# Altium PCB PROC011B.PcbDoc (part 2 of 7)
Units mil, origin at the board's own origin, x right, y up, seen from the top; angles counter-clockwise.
Board outline 3304 x 2569 mil, 6 copper layers (TOP, L2-GND1, L3-GND/SIG, L4-GND/SIG, L5-GND2, BOTTOM), stack 55.77 mil thick; 376 components, 289 nets, 1284 pads, 1755 vias.
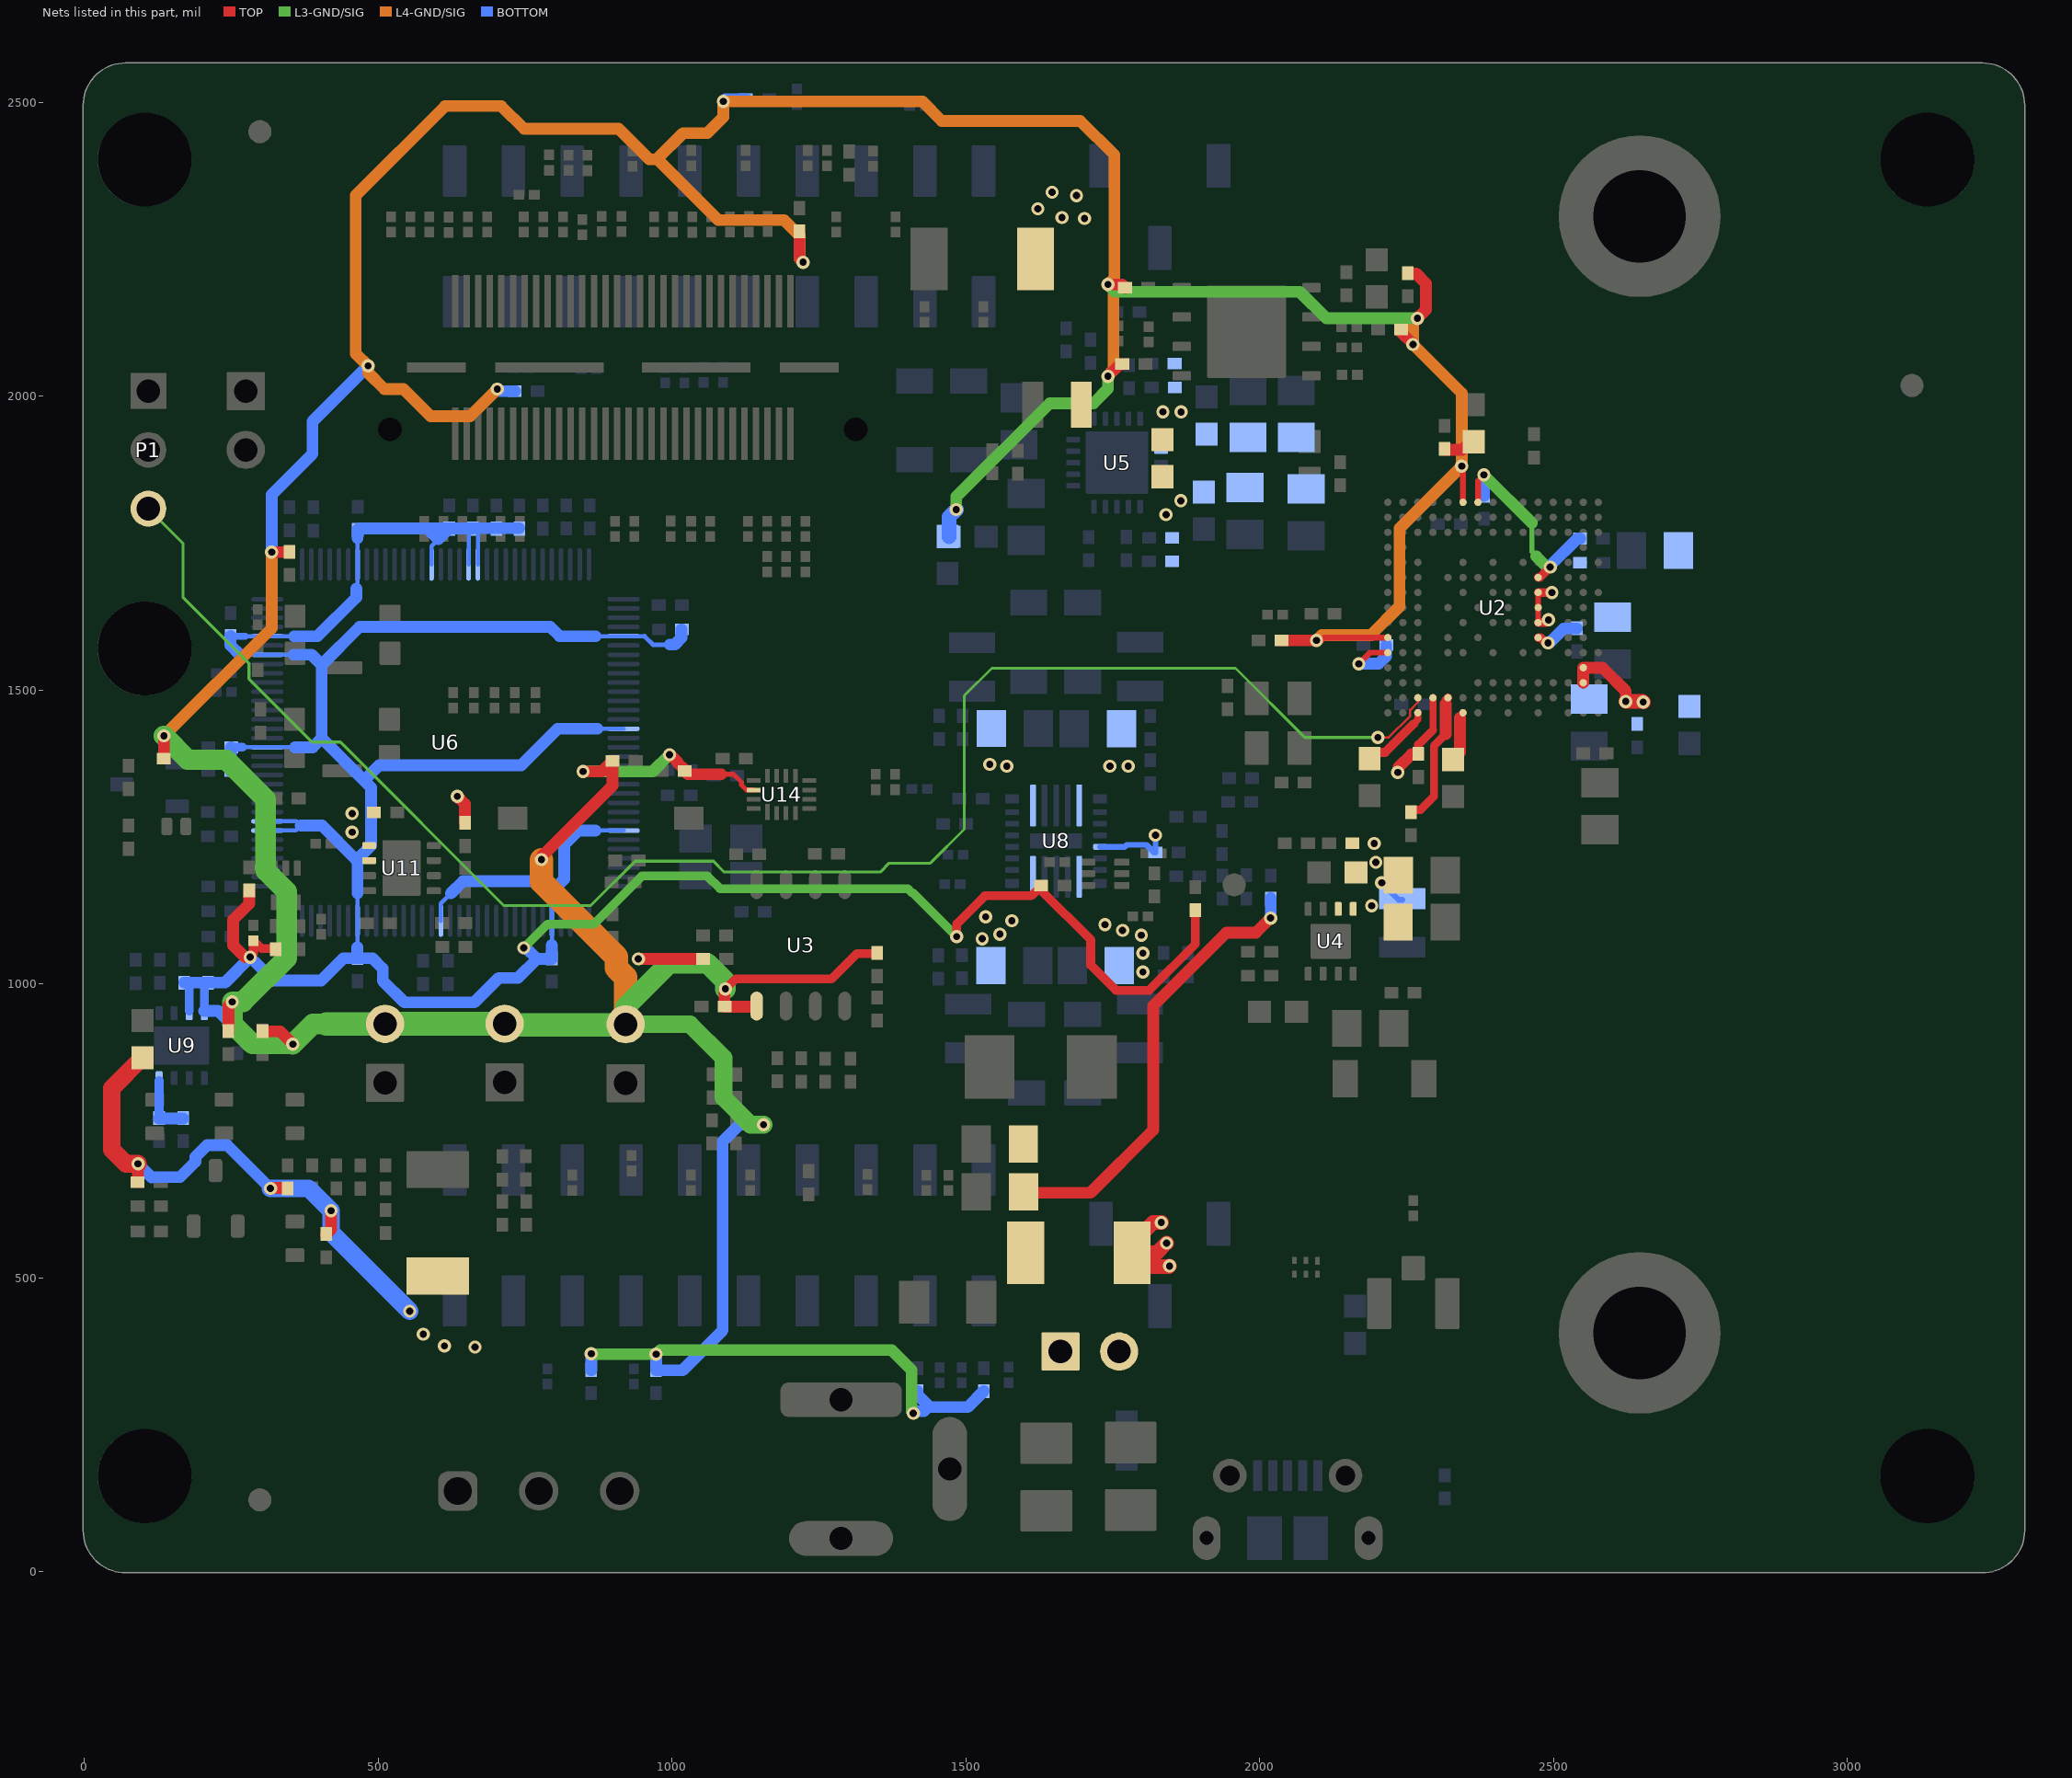
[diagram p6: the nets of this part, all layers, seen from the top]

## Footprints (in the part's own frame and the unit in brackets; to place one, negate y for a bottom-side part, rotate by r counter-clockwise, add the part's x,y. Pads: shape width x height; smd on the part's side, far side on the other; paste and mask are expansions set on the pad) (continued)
PDT0128A [mm] "Thin QFP, 128-Leads, Body 14x14mm, Pitch 0.4mm"
  oval 1.4x0.2 smd: 1(-7.7,6.2) 2(-7.7,5.8) 3(-7.7,5.4) 4(-7.7,5) 5(-7.7,4.6) 6(-7.7,4.2) 7(-7.7,3.8) 8(-7.7,3.4) 9(-7.7,3) 10(-7.7,2.6) 11(-7.7,2.2) 12(-7.7,1.8) 13(-7.7,1.4) 14(-7.7,1) 15(-7.7,0.6) 16(-7.7,0.2) 17(-7.7,-0.2) 18(-7.7,-0.6) 19(-7.7,-1) 20(-7.7,-1.4) 21(-7.7,-1.8) 22(-7.7,-2.2) 23(-7.7,-2.6) 24(-7.7,-3) 25(-7.7,-3.4) 26(-7.7,-3.8) 27(-7.7,-4.2) 28(-7.7,-4.6) 29(-7.7,-5) 30(-7.7,-5.4) 31(-7.7,-5.8) 32(-7.7,-6.2) 65(7.7,-6.2) 66(7.7,-5.8) 67(7.7,-5.4) 68(7.7,-5) 69(7.7,-4.6) 70(7.7,-4.2) 71(7.7,-3.8) 72(7.7,-3.4) 73(7.7,-3) 74(7.7,-2.6) 75(7.7,-2.2) 76(7.7,-1.8) 77(7.7,-1.4) 78(7.7,-1) 79(7.7,-0.6) 80(7.7,-0.2) 81(7.7,0.2) 82(7.7,0.6) 83(7.7,1) 84(7.7,1.4) 85(7.7,1.8) 86(7.7,2.2) 87(7.7,2.6) 88(7.7,3) 89(7.7,3.4) 90(7.7,3.8) 91(7.7,4.2) 92(7.7,4.6) 93(7.7,5) 94(7.7,5.4) 95(7.7,5.8) 96(7.7,6.2)
  oval 0.2x1.4 smd: 33(-6.2,-7.7) 34(-5.8,-7.7) 35(-5.4,-7.7) 36(-5,-7.7) 37(-4.6,-7.7) 38(-4.2,-7.7) 39(-3.8,-7.7) 40(-3.4,-7.7) 41(-3,-7.7) 42(-2.6,-7.7) 43(-2.2,-7.7) 44(-1.8,-7.7) 45(-1.4,-7.7) 46(-1,-7.7) 47(-0.6,-7.7) 48(-0.2,-7.7) 49(0.2,-7.7) 50(0.6,-7.7) 51(1,-7.7) 52(1.4,-7.7) 53(1.8,-7.7) 54(2.2,-7.7) 55(2.6,-7.7) 56(3,-7.7) 57(3.4,-7.7) 58(3.8,-7.7) 59(4.2,-7.7) 60(4.6,-7.7) 61(5,-7.7) 62(5.4,-7.7) 63(5.8,-7.7) 64(6.2,-7.7) 97(6.2,7.7) 98(5.8,7.7) 99(5.4,7.7) 100(5,7.7) 101(4.6,7.7) 102(4.2,7.7) 103(3.8,7.7) 104(3.4,7.7) 105(3,7.7) 106(2.6,7.7) 107(2.2,7.7) 108(1.8,7.7) 109(1.4,7.7) 110(1,7.7) 111(0.6,7.7) 112(0.2,7.7) 113(-0.2,7.7) 114(-0.6,7.7) 115(-1,7.7) 116(-1.4,7.7) 117(-1.8,7.7) 118(-2.2,7.7) 119(-2.6,7.7) 120(-3,7.7) 121(-3.4,7.7) 122(-3.8,7.7) 123(-4.2,7.7) 124(-4.6,7.7) 125(-5,7.7) 126(-5.4,7.7) 127(-5.8,7.7) 128(-6.2,7.7)
  silkscreen extent -7.7,-6.3 6.3,6.99, body extent -8,-8 8,8, height 1.07
RNF0026C [mm] "QFN, 26-Leads, Body 4x4.5mm, Pitch 0.5mm"
  rrect25% 0.6x0.4 smd paste-0.3: 1(-1.9,1.825) 8(-1.9,-1.825) 14(1.9,-1.825) 21(1.9,1.825)
  rrect40% 0.6x0.25 smd paste+0: 2(-1.9,1.25) 3(-1.9,0.75) 4(-1.9,0.25) 5(-1.9,-0.25) 6(-1.9,-0.75) 7(-1.9,-1.25) 15(1.9,-1.25) 16(1.9,-0.75) 17(1.9,-0.25) 18(1.9,0.25) 19(1.9,0.75) 20(1.9,1.25)
  rrect40% 0.25x1.82 smd paste-1: 9(-1,-1.54) 10(-0.5,-1.54) 11(0,-1.54) 12(0.5,-1.54) 13(1,-1.54) 22(1,1.54) 23(0.5,1.54) 24(0,1.54) 25(-0.5,1.54) 26(-1,1.54)
  rrect15% 2.24x0.66 smd paste-1: 27(0,0)
  rrect50% 0.6x0.3 on Bottom Paste: ""(-1.9,-1.775) ""(-1.9,1.775) ""(1.9,-1.775) ""(1.9,1.775)
  rrect50% 0.3x0.825 on Bottom Paste: ""(-1.575,-2.037) ""(-1.575,2.037) ""(1.575,-2.037) ""(1.575,2.037)
  rrect50% 0.25x0.81 on Bottom Paste: ""(-1,-2.045) ""(-1,-1.035) ""(-1,1.035) ""(-1,2.045) ""(-0.5,-2.045) ""(-0.5,-1.035) ""(-0.5,1.035) ""(-0.5,2.045) ""(0,-2.045) ""(0,-1.035) ""(0,1.035) ""(0,2.045) ""(0.5,-2.045) ""(0.5,-1.035) ""(0.5,1.035) ""(0.5,2.045) ""(1,-2.045) ""(1,-1.035) ""(1,1.035) ""(1,2.045)
  rrect50% 0.98x0.66 on Bottom Paste: ""(-0.59,0) ""(0.59,0)
  TOP region: -1.775,-2.4 -1.775,-1.675 -1.775,-1.665 -1.767,-1.647 -1.753,-1.633 -1.735,-1.625 -1.725,-1.625 -1.725,-1.625 -1.475,-1.625 -1.465,-1.625 -1.447,-1.633 -1.433,-1.647 -1.425,-1.665 -1.425,-1.675 -1.425,-1.675 -1.425,-2.4 -1.425,-2.41 -1.433,-2.428 -1.447,-2.442 -1.465,-2.45 -1.475,-2.45 -1.475,-2.45 -1.725,-2.45 -1.735,-2.45 -1.753,-2.442 -1.767,-2.428 -1.775,-2.41 -1.775,-2.4
  TOP region: 1.425,-2.4 1.425,-1.675 1.425,-1.665 1.433,-1.647 1.447,-1.633 1.465,-1.625 1.475,-1.625 1.475,-1.625 1.725,-1.625 1.735,-1.625 1.753,-1.633 1.767,-1.647 1.775,-1.665 1.775,-1.675 1.775,-1.675 1.775,-2.4 1.775,-2.41 1.767,-2.428 1.753,-2.442 1.735,-2.45 1.725,-2.45 1.725,-2.45 1.475,-2.45 1.465,-2.45 1.447,-2.442 1.433,-2.428 1.425,-2.41 1.425,-2.4
  TOP region: 1.425,1.675 1.425,2.4 1.425,2.41 1.433,2.428 1.447,2.442 1.465,2.45 1.475,2.45 1.475,2.45 1.725,2.45 1.735,2.45 1.753,2.442 1.767,2.428 1.775,2.41 1.775,2.4 1.775,2.4 1.775,1.675 1.775,1.665 1.767,1.647 1.753,1.633 1.735,1.625 1.725,1.625 1.725,1.625 1.475,1.625 1.465,1.625 1.447,1.633 1.433,1.647 1.425,1.665 1.425,1.675
  TOP region: -1.775,1.675 -1.775,2.4 -1.775,2.41 -1.767,2.428 -1.753,2.442 -1.735,2.45 -1.725,2.45 -1.725,2.45 -1.475,2.45 -1.465,2.45 -1.447,2.442 -1.433,2.428 -1.425,2.41 -1.425,2.4 -1.425,2.4 -1.425,1.675 -1.425,1.665 -1.433,1.647 -1.447,1.633 -1.465,1.625 -1.475,1.625 -1.475,1.625 -1.725,1.625 -1.735,1.625 -1.753,1.633 -1.767,1.647 -1.775,1.665 -1.775,1.675
  silkscreen extent -2.45,-2.7 2.45,2.7, body extent -2,-2.25 2,2.25, height 0.9
RSV0016A [mm] "QFN, 16-Leads, Body 1.8x2.6mm, Pitch 0.4mm, TI Recommended"
  rect 0.7x0.2 smd: 1(-0.75,0.6)
  rect 0.6x0.2 smd: 2(-0.8,0.2) 3(-0.8,-0.2) 4(-0.8,-0.6) 9(0.8,-0.6) 10(0.8,-0.2) 11(0.8,0.2) 12(0.8,0.6)
  rect 0.2x0.6 smd: 5(-0.6,-1.2) 6(-0.2,-1.2) 7(0.2,-1.2) 8(0.6,-1.2) 13(0.6,1.2) 14(0.2,1.2) 15(-0.2,1.2) 16(-0.6,1.2)
  silkscreen extent -1.08,-1.33 1.08,1.45, body extent -0.92,-1.32 0.92,1.33, height 0.56
RTJ0020D [mm] "QFN, 20-Leads, Body 4x4mm, Pitch 0.5mm, Thermal Pad 2.7x2.7mm, TI Recommended"
  rrect42% 0.6x0.24 smd: 1(-1.9,1) 2(-1.9,0.5) 3(-1.9,0) 4(-1.9,-0.5) 5(-1.9,-1) 11(1.9,-1) 12(1.9,-0.5) 13(1.9,0) 14(1.9,0.5) 15(1.9,1)
  rrect42% 0.24x0.6 smd: 6(-1,-1.9) 7(-0.5,-1.9) 8(0,-1.9) 9(0.5,-1.9) 10(1,-1.9) 16(1,1.9) 17(0.5,1.9) 18(0,1.9) 19(-0.5,1.9) 20(-1,1.9)
  rrect50% 1.19x1.19 on Bottom Paste: 21(-0.695,-0.695) 21(-0.695,0.695) 21(0.695,-0.695) 21(0.695,0.695)
  rrect4% 2.7x2.7 smd paste-1.4: 21(0,0)
  silkscreen extent -2.22,-2.22 2.23,2.22, body extent -2.07,-2.07 2.08,2.08, height 0.8
SAMTEC_QSH-030-01-X-D-A [mm] "Receptacle, 0.5 mm, 30x2, TH"
  rect 2.27x0.279 smd: 1(-2.865,7.25) 2(2.865,7.25) 3(-2.865,6.75) 4(2.865,6.75) 5(-2.865,6.25) 6(2.865,6.25) 7(-2.865,5.75) 8(2.865,5.75) 9(-2.865,5.25) 10(2.865,5.25) 11(-2.865,4.75) 12(2.865,4.75) 13(-2.865,4.25) 14(2.865,4.25) 15(-2.865,3.75) 16(2.865,3.75) 17(-2.865,3.25) 18(2.865,3.25) 19(-2.865,2.75) 20(2.865,2.75) 21(-2.865,2.25) 22(2.865,2.25) 23(-2.865,1.75) 24(2.865,1.75) 25(-2.865,1.25) 26(2.865,1.25) 27(-2.865,0.75) 28(2.865,0.75) 29(-2.865,0.25) 30(2.865,0.25) 31(-2.865,-0.25) 32(2.865,-0.25) 33(-2.865,-0.75) 34(2.865,-0.75) 35(-2.865,-1.25) 36(2.865,-1.25) 37(-2.865,-1.75) 38(2.865,-1.75) 39(-2.865,-2.25) 40(2.865,-2.25) 41(-2.865,-2.75) 42(2.865,-2.75) 43(-2.865,-3.25) 44(2.865,-3.25) 45(-2.865,-3.75) 46(2.865,-3.75) 47(-2.865,-4.25) 48(2.865,-4.25) 49(-2.865,-4.75) 50(2.865,-4.75) 51(-2.865,-5.25) 52(2.865,-5.25) 53(-2.865,-5.75) 54(2.865,-5.75) 55(-2.865,-6.25) 56(2.865,-6.25) 57(-2.865,-6.75) 58(2.865,-6.75) 59(-2.865,-7.25) 60(2.865,-7.25)
  round 0 hole 1.02 unplated mask+0.127: MH1(2.67,10.065) MH2(2.67,-10.065)
  rect 0.43x2.54 smd: MP1(0,8.065) MP4(0,-8.065)
  rect 0.43x4.7 smd: MP2(0,3.175) MP3(0,-3.175)
  silkscreen extent -3.9,-10.66 3.62,10.66, body extent -3.75,-10.64 3.75,10.67, height 3.25
SAMTEC_SSM-103-X-SV [mm] "Receptacle, 2.54mm, 3x1, SMT"
  rrect10% 1.02x1.905 smd: 1(-2.54,-1.777) 2(0,1.777) 3(2.54,-1.777)
  silkscreen extent -3.81,-2.27 3.81,1.28, body extent -3.81,-2.29 3.81,2.29, height 7.51
SAMTEC_SSM-110-X-DV [mm] "Receptacle, 2.54mm, 10x2, SMT"
  rrect10% 1.02x2.22 smd: 1(-11.43,2.825) 2(-11.43,-2.825) 3(-8.89,2.825) 4(-8.89,-2.825) 5(-6.35,2.825) 6(-6.35,-2.825) 7(-3.81,2.825) 8(-3.81,-2.825) 9(-1.27,2.825) 10(-1.27,-2.825) 11(1.27,2.825) 12(1.27,-2.825) 13(3.81,2.825) 14(3.81,-2.825) 15(6.35,2.825) 16(6.35,-2.825) 17(8.89,2.825) 18(8.89,-2.825) 19(11.43,2.825) 20(11.43,-2.825)
  silkscreen extent -13.02,-2.54 12.7,2.54, body extent -12.7,-3.52 12.7,3.52, height 7.42
SAMTEC_TSW-103-07-T-S [mm] "Header, 2.54 mm, 3x1, TH"
  rect 1.55x1.55 hole 1.02: 1(-2.54,0)
  round 1.55 hole 1.02: 2(0,0) 3(2.54,0)
  silkscreen extent -3.81,-1.75 3.81,1.27, body extent -3.81,-1.27 3.81,1.27, height 8.39
SMB [mil] "Molded Diode, 2-Leads, Body 5.4x3.6mm, IPC Medium Density, based on OnSemi component dimensions"
  rect 85x107.99 smd: 1(-87.01,0) 2(87.01,0)
  silkscreen extent -155,-82 125,82, body extent -106,-71 106,71, height 91
SOD-882 [mm] "Skyworks"
  rrect42% 0.475x0.75 smd: 1(-0.412,0) 2(0.412,0)
  silkscreen extent -1.1,-0.35 -0.87,0.35, body extent -0.5,-0.3 0.5,0.3, height 0.5
SOT-23 [mm] "SOT23, 3-Leads, Body 2.9x1.3mm, Pitch 0.95mm, Lead Span 2.5mm, IPC Medium Density"
  rrect50% 1x0.6 smd: 1(-1.2,0.95) 2(-1.2,-0.95) 3(1.2,0)
  silkscreen extent -1.62,-1.5 0.7,1.5, body extent -1.16,-1.45 1.21,1.45, height 1
SW_CHS-01TB [mm] "CHS Recommended footprint"
  rect 1x1.27 smd: 1(0,3.81) 2(0,-3.81)
  silkscreen extent -1.8,-4.05 1.3,4.05, body extent -1.25,-4 1.25,4, height 2.51
SW_KMR243GLFG [mm] "SMD, 5-Leads, Body 4.2x2.8mm"
  rrect11% 0.9x1 smd: 1(-2.05,0.8) 2(2.05,0.8) 3(-2.05,-0.8) 4(2.05,-0.8)
  rrect18% 1.7x0.55 smd: 5(0,1.425)
  silkscreen extent -3.1,0.7 -2.9,0.9, body extent -2.3,-1.4 2.3,1.4, height 1.92
TI_Stacked_Overlay_Small [mil]
  silkscreen extent -418,-98 418,98
TLMX1000_RED [mm] "SMD, 2-Leads, Body 1.6x0.8mm"
  rrect17% 0.6x0.8 smd: 1(-0.725,0) 2(0.725,0)
  silkscreen extent -0.97,-0.8 1.6,0.8, body extent -0.85,-0.45 0.85,0.45, height 0.65
TLMX1000_YELLOW [mm] "SMD, 2-Leads, Body 1.6x0.8mm"
  rrect17% 0.6x0.8 smd: 1(-0.725,0) 2(0.725,0)
  silkscreen extent -0.97,-0.8 1.6,0.8, body extent -0.85,-0.45 0.85,0.45, height 0.65
TSW-102-07-X-S [mm] "Samtec 100 mil 1x2 head, 230 mil above insulator"
  rrect6% 1.65x1.65 hole 1.016: 1(-1.27,0)
  round 1.65 hole 1.016: 2(1.27,0)
  silkscreen extent -3.42,-1.4 2.72,1.4, body extent -2.54,-1.27 2.54,1.27, height 8.38
WEEE_Minimum [mil] "WEEElie bin"
  silkscreen extent -95,-172 99,104
WSON-8L_6x5MM_EP [mm] "SMD, 8-Leads, Body 6x5mm, Pitch 1.27mm"
  rrect25% 0.8x0.4 smd: 1(-2.8,1.905) 2(-2.8,0.635) 3(-2.8,-0.635) 4(-2.8,-1.905) 5(2.8,-1.905) 6(2.8,-0.635) 7(2.8,0.635) 8(2.8,1.905)
  rrect3% 3.4x4 smd paste-3: 9(0,0)
  rrect7% 1.468x1.698 on Top Paste: ""(-0.834,-0.949) ""(-0.834,0.949) ""(0.834,-0.949) ""(0.834,0.949)
  silkscreen extent -3.2,-2.7 3.2,2.7, body extent -3.05,-2.55 3.05,2.55, height 0.8

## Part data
C1 C13 C14 C33 C36: library part CMP-0007136-5, "CAP, CERM, 1 uF, 16 V, +/- 10%, X7R, AEC-Q200 Grade 1, 0603", Cap_Case=0603, Manufacturer=MuRata, Supplier Part Number 1=490-5241-6-ND, TempCo=X7R, Tolerance_%=10%, Value1=Unknown, Value2=16V, ValueDisplayed=1uF
C2 C21: library part CMP-0006325-2, "CAP, CERM, 0.1 uF, 50 V, +/- 10%, X7R, AEC-Q200 Grade 1, 0402", Cap_Case=0402, Manufacturer=TDK, Supplier Part Number 1=445-6899-1-ND, TempCo=X7R, Tolerance_%=10%, Value1="0.039064 ohm", Value2=50V, ValueDisplayed=0.1uF
C3 C5 C7 C10 C12 C39 C47 C48 C51 C53 C56 C57 C68 C84 C90: library part CMP-0078265-1, "CAP, CERM, 0.22 µF, 16 V,+/- 10%, X7R, AEC-Q200 Grade 1, 0402", Cap_Case=0402, Manufacturer=MuRata, Supplier Part Number 1=490-10671-1-ND, TempCo=X7R, Tolerance_%=10%, Value2=16V, ValueDisplayed=0.22µF
C4 C6 C11: library part CMP-0006351-2, "CAP, CERM, 0.1 uF, 16 V, +/- 10%, X7R, 0402", Cap_Case=0402, Manufacturer=MuRata, Supplier Part Number 1=490-4759-2-ND, TempCo=X7R, Tolerance_%=10%, Value1=Unknown, Value2=16V, ValueDisplayed=0.1uF
C8: library part CMP-0078219-1, "CAP, CERM, 0.1 µF, 10 V,+/- 10%, X7S, 0201", Cap_Case=0201, Manufacturer=TDK, Supplier Part Number 1=445-9051-1-ND, TempCo=X7S, Tolerance_%=10%, Value2=10V, ValueDisplayed=0.1µF
C9 C15: library part CMP-0006367-2, "CAP, CERM, 4.7 pF, 50 V, +/- 2%, C0G/NP0, 0402", Cap_Case=0402, Manufacturer=MuRata, Supplier Part Number 1=490-8102-1-ND, TempCo=C0G/NP0, Tolerance_%=2%, Value1=Unknown, Value2=50V, ValueDisplayed=4.7pF
C16 C20 C42 C43 C49 C64 C67 C71 C75 C76 C79 C91 C92 C97: library part CMP-0078241-1, "CAP, CERM, 0.1 µF, 10 V,+/- 10%, X7R, 0402", Cap_Case=0402, Manufacturer=Kemet, Supplier Part Number 1=399-3520-1-ND, TempCo=X7R, Tolerance_%=10%, Value2=10V, ValueDisplayed=0.1µF
C17 C19 C23 C32 C34 C35 C37 C38 C40 C45 C52 C58 C59 C60 C65 C72 C73 C83: library part CMP-0008017-2, "CAP, CERM, 10 uF, 10 V, +/- 10%, X7R, 0805", Cap_Case=0805, Manufacturer=MuRata, Supplier Part Number 1=490-10674-1-ND, TempCo=X7R, Tolerance_%=10%, Value1=Unknown, Value2=10V, ValueDisplayed=10uF
C18 C22: library part CMP-0007138-4, "CAP, CERM, 0.47 uF, 16 V, +/- 10%, X7R, AEC-Q200 Grade 1, 0603", Cap_Case=0603, Manufacturer=MuRata, Supplier Part Number 1=490-4775-1-ND, TempCo=X7R, Tolerance_%=10%, Value1=Unknown, Value2=16V, ValueDisplayed=0.47uF
C24: library part CMP-0078221-1, "CAP, CERM, 4700 pF, 50 V,+/- 10%, X7R, 0402", Cap_Case=0402, Manufacturer=TDK, Supplier Part Number 1=445-1258-1-ND, TempCo=X7R, Tolerance_%=10%, Value2=50V, ValueDisplayed=4700pF
C25 C30 C31: library part CMP-0008770-2, "CAP, CERM, 22 uF, 6.3 V, +/- 10%, X7R, AEC-Q200 Grade 1, 1206", Cap_Case=1206_180, Manufacturer=TDK, Supplier Part Number 1=445-7884-1-ND, TempCo=X7R, Tolerance_%=10%, Value1="0.001872 ohm", Value2=6.3V, ValueDisplayed=22uF
C26 C27: library part CMP-0078216-1, "CAP, TA, 47 µF, 10 V, +/- 10%, SMD", Cap_Case=3528-21, Manufacturer=Kemet, Supplier Part Number 1=399-9728-1-ND, Tolerance_%=10%, Value2=10V, ValueDisplayed=47µF
C28 C29 C44 C46: library part CMP-0078224-1, "CAP, CERM, 0.01 µF, 50 V,+/- 10%, X8R, AEC-Q200 Grade 0, 0402", Cap_Case=0402, Manufacturer=TDK, Supplier Part Number 1=445-12303-1-ND, TempCo=X8R, Tolerance_%=10%, Value2=50V, ValueDisplayed=0.01µF
C41 C61 C62 C85: library part CMP-0078222-1, "CAP, CERM, 1 µF, 6.3 V,+/- 20%, X7S, 0402", Cap_Case=0402, Manufacturer=TDK, Supplier Part Number 1=445-9080-1-ND, TempCo=X7S, Tolerance_%=20%, Value2=6.3V, ValueDisplayed=1µF
C50: library part CMP-0078220-1, "CAP, CERM, 0.01 µF, 25 V,+/- 10%, X7R, 0402", Cap_Case=0402, Manufacturer=TDK, Supplier Part Number 1=445-1260-1-ND, TempCo=X7R, Tolerance_%=10%, Value2=25V, ValueDisplayed=0.01µF
C54 C55 C81 C82: library part CMP-0008811-2, "CAP, CERM, 22 uF, 10 V, +/- 10%, X7R, AEC-Q200 Grade 1, 1206", Cap_Case=1206, Manufacturer=MuRata, TempCo=X7R, Tolerance_%=10%, Value1=Unknown, Value2=10V, ValueDisplayed=22uF
C63 C70: library part CMP-0006494-2, "CAP, CERM, 8 pF, 50 V, +/- 6%, C0G/NP0, 0402", Cap_Case=0402, Manufacturer=MuRata, Supplier Part Number 1=490-5867-1-ND, TempCo=C0G/NP0, Tolerance_%=6%, Value1=Unknown, Value2=50V, ValueDisplayed=8pF
C66 C69: library part CMP-0078218-1, "CAP, CERM, 0.01 µF, 16 V,+/- 10%, X7R, 0402", Cap_Case=0402, Manufacturer=Kemet, Supplier Part Number 1=399-1038-1-ND, TempCo=X7R, Tolerance_%=10%, Value2=16V, ValueDisplayed=0.01µF
C74 C77 C80 C86: library part CMP-0006302-2, "CAP, CERM, 2.2 uF, 10 V, +/- 10%, X7S, 0402", Cap_Case=0402_065, Manufacturer=TDK, Supplier Part Number 1=445-9097-1-ND, TempCo=X7S, Tolerance_%=10%, Value1="0.005925 ohm", Value2=10V, ValueDisplayed=2.2uF
C78: library part CMP-0078217-1, "CAP, CERM, 15 pF, 50 V,+/- 1%, C0G/NP0, 0402", Cap_Case=0402, Manufacturer=AVX, Supplier Part Number 1=478-5126-1-ND, TempCo=C0G/NP0, Tolerance_%=1%, Value2=50V, ValueDisplayed=15pF
C87 C89: library part CMP-0007134-5, "CAP, CERM, 2.2 uF, 6.3 V, +/- 10%, X7R, AEC-Q200 Grade 1, 0603", Cap_Case=0603, Manufacturer=MuRata, Supplier Part Number 1=490-5316-1-ND, TempCo=X7R, Tolerance_%=10%, Value1=Unknown, Value2=6.3V, ValueDisplayed=2.2uF
C88: library part CMP-0006242-2, "CAP, CERM, 33 pF, 50 V, +/- 5%, C0G/NP0, 0402", Cap_Case=0402, Manufacturer=Kemet, Supplier Part Number 1=399-1017-1-ND, TempCo=C0G/NP0, Tolerance_%=5%, Value1=Unknown, Value2=50V, ValueDisplayed=33pF
C93 C94 C95 C96: library part CMP-0078223-1, "CAP, CERM, 390 pF, 50 V,+/- 5%, C0G/NP0, AEC-Q200 Grade 0, 0402", Cap_Case=0402, Manufacturer=TDK, Supplier Part Number 1=445-12137-1-ND, TempCo=C0G/NP0, Tolerance_%=5%, Value2=50V, ValueDisplayed=390pF
"CAUTION HOT SURFACE": library part CMP-0074837-1, "IEC 61010-1 Hot Surface Warning"
D2: library part CMP-0078187-1, "Diode, Schottky,  V, 0.01 A, SOD-882", Manufacturer="Skyworks Solutions", Value1=0.01A, Value2=0.34V
D3: library part CMP-0078243-1, "Diode, TVS, Uni, 5.8 V, 10.5 Vc, AEC-Q101, SMB", Manufacturer=Littelfuse, Power_W=550mW, Supplier Part Number 1=SZP6SMB6.8AT3G-ND, Value1=0.55W
DS1 DS2: library part CMP-0078197-1, "LED, Red, SMD", Color=Red, Manufacturer=Vishay-Semiconductor, Power_TotalModule=40mW, Supplier Part Number 1=TLMS1000-GS08CT-ND, Value1=.04W, Value2=1.8V
DS3 DS4: library part CMP-0078196-1, "LED, Yellow, SMD", Color=yellow, Manufacturer=Vishay-Semiconductor, Power_TotalModule=40mW, Supplier Part Number 1=TLMY1000-GS08CT-ND, Value1=.04W, Value2=1.8V
"ESD Susceptible": library part CMP-0074840-1, "ESD Susceptible Symbol"
F1: library part CMP-0003458-1, "Fuse, 5 A, 32VAC/VDC, SMD", Irating_A=5A, Manufacturer=Littelfuse, Supplier Part Number 1=F1608CT-ND
FB1 FB2: library part CMP-0003364-1, "Ferrite Bead, 30 ohm @ 100 MHz, 4 A, 0805", Manufacturer=MuRata, Supplier Part Number 1=490-11049-1-ND, Value1="0.014 ohm", Value2=4A, ValueDisplayed="30 ohm"
FID1 FID2 FID3 FID4 FID5 FID6 FID7: library part CMP-0077181-1, "Fiducial mark.  There is nothing to buy or mount.", Manufacturer=N/A
J1: library part CMP-0075524-1, "Receptacle, 0.5 mm, 30x2, Gold, TH", Color=Black, Manufacturer=Samtec, Supplier Part Number 1=SAM8180-ND
J2: library part CMP-0055788-1, "UMC Straight Jack Receptacle, 50 Ohm, Gold, SMT", Manufacturer="Cinch Connectivity", Supplier Part Number 1=J983CT-ND
J3: library part CMP-0075352-1, "Terminal Block, 3.5mm, 3x1, Tin, R/A, TH", Color=Blue, Current_A=10A, Manufacturer="On-Shore Technology", Supplier Part Number 1=ED2636-ND, Voltage_V=125V
J4 J7: library part CMP-0078183-1, "Receptacle, 2.54mm, 3x1, Gold with Tin tail, SMT", Color=Black, Current_A=5.2A, Manufacturer=Samtec, Supplier Part Number 1=SAM1152-03-ND, Voltage_V=405V
J5 J6: library part CMP-0078182-1, "Receptacle, 2.54mm, 10x2, Gold with Tin tail, SMT", Color=Black, Current_A=5.2A, Manufacturer=Samtec, Supplier Part Number 1=SAM1150-10-ND, Voltage_V=405V
J8: library part CMP-0055293-1, "Connector, Receptacle, Micro-USB Type B, R/A, Bottom Mount SMT", Manufacturer=Molex, Supplier Part Number 1=WM1399CT-ND
L1 L2 L3 L4 L5 L6: library part CMP-0058946-1, "Inductor, Shielded, 470 nH, 4.7 A, 0.021 ohm, SMD", Manufacturer="MuRata Toko", PartNumber=DFE252012P-R47M{}P2, Value1="0.021 ohm", Value2=4.7A, ValueDisplayed=470nH
LBL1: library part THT-14-423-10, "Thermal Transfer Printable Labels, 0.650\" W x 0.200\" H - 10,000 per roll", Alternate Manufacturer=-, Manufacturer=Brady, Supplier Part Number 1=2065596
Logo1: library part CMP-0074838-1, "Texas Instrument Corporate Signature"
Logo2: library part CMP-0074769-1
Logo3: library part CMP-0074847-1, "FCC_disclaimer"
P1: library part CMP-0075530-1, "Header, 2.54 mm, 3x1, Tin, TH", Color=Black, Current_A=6.3A, Manufacturer=Samtec, Supplier Part Number 1=SAM1035-03-ND, Voltage_V=550V
P2 P3 P4 P5 P7: library part CMP-0075405-1, "Header, 100mil, 2x1, Gold, TH", Color=Black, Current_A=6.3A, Manufacturer=Samtec, Supplier Part Number 1=SAM1029-02-ND, Voltage_V=550V
P6: library part CMP-0078270-1, "DC POWER JACK, R/A, TH", Color=Black, Current_A=5A, Manufacturer="CUI Inc.", Supplier Part Number 1=CP-002AH-ND, Voltage_V=4.5-5.5V
Q1 Q2: library part CMP-0000947-2, "MOSFET, N-CH, 100 V, 0.17 A, SOT-23", Alternate Manufacturer=None, Manufacturer="Fairchild Semiconductor", Supplier Part Number 1=BSS123NCT-ND, Value1=1, Value2="1.8 nC"
R1 R2 R4 R5 R6 R7 R8 R9 R10 R17 R18 R19 R20 R21 R22 R23 R24 R25 R26 R27 R28 R29 R30 R31 R32 R33 R35 R36 R48 R49 R50 R51 R52 R53 R58 R59 R60 R62 R63 R64 R65 R66 R67 R69 R70 R71 R72 R75 R76 R94 R102 R104 R105 R106 R108 R109 R111 R135 R136 R144 R146 R162 R163 R164 R165 R166 R167 R168 R169 R198 R199 R201: library part CMP-0027008-3, "RES, 0, 5%, 0.05 W, 0201", Manufacturer=Vishay-Dale, Power_W=50mW, Supplier Part Number 1=72M6743, TempCo=ppm/C, Tolerance_%=5%, Value2=0.05W, Value_Code=0000, ValueDisplayed=0
R3 R13 R15 R16 R41 R43 R46 R47 R73 R74 R81 R83 R84 R86 R89 R91 R98 R113 R145 R148 R155 R170 R171 R177 R194 R197 R206 R208: library part CMP-0025958-2, "RES, 10.0 k, 1%, 0.063 W, 0402", Manufacturer=Vishay-Dale, Power_W=63mW, Supplier Part Number 1=541-10.0KLCT-ND, TempCo="100 ppm/C", Tolerance_%=1%, Value2=0.063W, Value_Code=10k0, ValueDisplayed=10.0k
R11 R12 R37 R78 R97 R107 R119 R120 R128 R129 R141 R152 R159 R178 R196 R200: library part CMP-0026992-2, "RES, 0, 5%, 0.063 W, 0402", Manufacturer=Panasonic, Power_W=63mW, Supplier Part Number 1=P0.0JCT-ND, TempCo="600 ppm/C", Tolerance_%=5%, Value2=0.063W, Value_Code=0000, ValueDisplayed=0
R14 R110 R138 R158 R172 R173: library part CMP-0025950-2, "RES, 100 k, 1%, 0.063 W, 0402", Manufacturer=Vishay-Dale, Power_W=63mW, Supplier Part Number 1=541-100KLCT-ND, TempCo="100 ppm/C", Tolerance_%=1%, Value2=0.063W, Value_Code=100k
R34 R115 R118: library part CMP-0016044-2, "RES, 0, 5%, 0.75 W, AEC-Q200 Grade 0, 2010", Manufacturer=Vishay-Dale, Power_W=750mW, Supplier Part Number 1=541-0.0WCT-ND, TempCo=ppm/C, Tolerance_%=5%, Value2=0.75W, Value_Code=0000, ValueDisplayed=0
R38: library part CMP-0026395-1, "RES, 47.5 k, 1%, 0.063 W, 0402", Manufacturer=Vishay-Dale, Power_W=63mW, Supplier Part Number 1=541-47.5KLCT-ND, TempCo="100 ppm/C", Tolerance_%=1%, Value2=0.063W, Value_Code=47k5, ValueDisplayed=47.5k
R39 R40 R42 R44 R45: library part CMP-0027275-2, "RES, 33.2, 1%, 0.05 W, 0201", Manufacturer=Vishay-Dale, Power_W=50mW, Supplier Part Number 1=541-33.2ABCT-ND, TempCo="200 ppm/C", Tolerance_%=1%, Value2=0.05W, Value_Code=33R2, ValueDisplayed=33.2
R54 R55 R56 R57 R179 R180 R181 R182 R183 R184 R185 R186 R187 R188 R189 R190 R191 R192: library part CMP-0078192-1, "RES, 20.0, 1%, 0.05 W, 0201", Manufacturer=Vishay-Dale, Power_W=50mW, Supplier Part Number 1=541-2947-1-ND, TempCo="200 ppm/C", Tolerance_%=1%, Value2=0.05W, Value_Code=20R0, ValueDisplayed=20.0
R61: library part CMP-0026015-2, "RES, 14.0 k, 1%, 0.063 W, 0402", Manufacturer=Vishay-Dale, Power_W=63mW, Supplier Part Number 1=541-14.0KLCT-ND, TempCo="100 ppm/C", Tolerance_%=1%, Value2=0.063W, Value_Code=14k0, ValueDisplayed=14.0k
R68 R77 R79 R80 R154: library part CMP-0026993-2, "RES, 100, 5%, 0.1 W, AEC-Q200 Grade 0, 0402", Manufacturer=Panasonic, Power_W=100mW, Supplier Part Number 1=P100JCT-ND, TempCo="200 ppm/C", Tolerance_%=5%, Value2=0.1W, Value_Code=100R, ValueDisplayed=100
R82: library part CMP-0025993-2, "RES, 12.7 k, 1%, 0.063 W, 0402", Manufacturer=Vishay-Dale, Power_W=63mW, Supplier Part Number 1=541-12.7KLCT-ND, TempCo="100 ppm/C", Tolerance_%=1%, Value2=0.063W, Value_Code=12k7, ValueDisplayed=12.7k
R85 R87: library part CMP-0026491-1, "RES, 61.9, 1%, 0.063 W, 0402", Manufacturer=Vishay-Dale, Power_W=63mW, Supplier Part Number 1=541-61.9LCT-ND, TempCo="100 ppm/C", Tolerance_%=1%, Value2=0.063W, Value_Code=61R9, ValueDisplayed=61.9
R88 R96 R114: library part CMP-0026574-1, "RES, 82.5 k, 1%, 0.063 W, AEC-Q200 Grade 0, 0402", Manufacturer=Vishay-Dale, Power_W=63mW, Supplier Part Number 1=541-82.5KLCT-ND, TempCo="100 ppm/C", Tolerance_%=1%, Value2=0.063W, Value_Code=82k5, ValueDisplayed=82.5k
R90: library part CMP-0078194-1, "RES, 360, 5%, 0.1 W, AEC-Q200 Grade 0, 0402", Manufacturer=Panasonic, Power_W=100mW, Supplier Part Number 1=P360JCT-ND, TempCo="200 ppm/C", Tolerance_%=5%, Value2=0.1W, Value_Code=360R, ValueDisplayed=360
R92 R95 R99: library part CMP-0026557-1, "RES, 7.87 k, 1%, 0.063 W, AEC-Q200 Grade 0, 0402", Manufacturer=Vishay-Dale, Power_W=63mW, Supplier Part Number 1=541-7.87KLCT-ND, TempCo="100 ppm/C", Tolerance_%=1%, Value2=0.063W, Value_Code=7k87, ValueDisplayed=7.87k
R93 R101 R112: library part CMP-0026542-1, "RES, 750, 1%, 0.063 W, AEC-Q200 Grade 0, 0402", Manufacturer=Vishay-Dale, Power_W=63mW, Supplier Part Number 1=541-750LCT-ND, TempCo="100 ppm/C", Tolerance_%=1%, Value2=0.063W, Value_Code=750R, ValueDisplayed=750
R100 R103 R116 R117 R160: library part CMP-0078212-1, "RES, 510, 5%, 0.1 W, AEC-Q200 Grade 0, 0402", Manufacturer=Panasonic, Power_W=100mW, Supplier Part Number 1=P510JCT-ND, TempCo="200 ppm/C", Tolerance_%=5%, Value2=0.1W, Value_Code=510R, ValueDisplayed=510
R121 R132: library part CMP-0078211-1, "RES, 3.00 k, 1%, 0.063 W, AEC-Q200 Grade 0, 0402", Manufacturer=Vishay-Dale, Power_W=63mW, Supplier Part Number 1=52K6934, TempCo="100 ppm/C", Tolerance_%=1%, Value2=0.063W, Value_Code=3k00, ValueDisplayed=3.00k
R122 R131 R139: library part CMP-0026099-1, "RES, 1.96 k, 1%, 0.063 W, 0402", Manufacturer=Vishay-Dale, Power_W=63mW, Supplier Part Number 1=541-1.96KLCT-ND, TempCo="100 ppm/C", Tolerance_%=1%, Value2=0.063W, Value_Code=1k96, ValueDisplayed=1.96k
R123 R124 R126 R127 R140: library part CMP-0026071-2, "RES, 1.00 k, 1%, 0.063 W, 0402", Manufacturer=Vishay-Dale, Power_W=63mW, Supplier Part Number 1=541-1.00KLCT-ND, TempCo="100 ppm/C", Tolerance_%=1%, Value2=0.063W, Value_Code=1k00, ValueDisplayed=1.00k
R125: library part CMP-0026413-1, "RES, 4.87 k, 1%, 0.063 W, 0402", Manufacturer=Vishay-Dale, Power_W=63mW, Supplier Part Number 1=541-4.87KLCT-ND, TempCo="100 ppm/C", Tolerance_%=1%, Value2=0.063W, Value_Code=4k87, ValueDisplayed=4.87k
R130 R133 R137 R161 R175 R176 R195: library part CMP-0025884-3, "RES, 0, 5%, 0.125 W, 0603", Manufacturer=Vishay/Beyschlag, Power_W=125mW, Supplier Part Number 1=MCT0603-0.0-ZZCT-ND, TempCo=ppm/C, Tolerance_%=5%, Value2=0.125W, Value_Code=0000, ValueDisplayed=0
R134: library part CMP-0026404-1, "RES, 49.9, 1%, 0.063 W, 0402", Manufacturer=Vishay-Dale, Power_W=63mW, Supplier Part Number 1=541-49.9LCT-ND, TempCo="100 ppm/C", Tolerance_%=1%, Value2=0.063W, Value_Code=49R9, ValueDisplayed=49.9
R142 R150: library part CMP-0026701-1, "RES, 4.99 k, 1%, 0.1 W, AEC-Q200 Grade 0, 0402", Manufacturer=Panasonic, Power_W=100mW, Supplier Part Number 1=P4.99KLCT-ND, TempCo="100 ppm/C", Tolerance_%=1%, Value2=0.1W, Value_Code=4k99, ValueDisplayed=4.99k
R143 R147: library part CMP-0026414-1, "RES, 4.99 k, 1%, 0.063 W, 0402", Manufacturer=Vishay-Dale, Power_W=63mW, Supplier Part Number 1=541-4.99KLCT-ND, TempCo="100 ppm/C", Tolerance_%=1%, Value2=0.063W, Value_Code=4k99, ValueDisplayed=4.99k
R149: library part CMP-0078193-1, "RES, 1.0 k, 5%, 0.1 W, AEC-Q200 Grade 0, 0402", Manufacturer=Panasonic, Power_W=100mW, Supplier Part Number 1=P1.0KJCT-ND, TempCo="200 ppm/C", Tolerance_%=5%, Value2=0.1W, Value_Code=1k00, ValueDisplayed=1.0k
R151 R153: library part CMP-0078210-1, "RES, 330 k, 1%, 0.063 W, AEC-Q200 Grade 0, 0402", Manufacturer=Vishay-Dale, Power_W=63mW, Supplier Part Number 1=541-330KLCT-ND, TempCo="100 ppm/C", Tolerance_%=1%, Value2=0.063W, Value_Code=330k
R156: library part CMP-0026403-1, "RES, 49.9 k, 1%, 0.063 W, 0402", Manufacturer=Vishay-Dale, Power_W=63mW, Supplier Part Number 1=541-49.9KLCT-ND, TempCo="100 ppm/C", Tolerance_%=1%, Value2=0.063W, Value_Code=49k9, ValueDisplayed=49.9k
R157 R174: library part CMP-0078244-1, "RES, 30.0 k, 1%, 0.063 W, AEC-Q200 Grade 0, 0402", Manufacturer=Vishay-Dale, Power_W=63mW, Supplier Part Number 1=541-30.0KLCT-ND, TempCo="100 ppm/C", Tolerance_%=1%, Value2=0.063W, Value_Code=30k0, ValueDisplayed=30.0k
R193: library part CMP-0078213-1, "RES, 35000, 0.1%, 0.05 W, 0402", Manufacturer=Vishay-Dale, Power_W=50mW, TempCo="25 ppm/C", Tolerance_%=0.1%, Value2=0.05W, Value_Code=35k0, ValueDisplayed=35000
R202 R203 R204 R205: library part CMP-0026363-1, "RES, 3.83, 1%, 0.063 W, 0402", Manufacturer=Vishay-Dale, Power_W=63mW, Supplier Part Number 1=541-3.83LLCT-ND, TempCo="100 ppm/C", Tolerance_%=1%, Value2=0.063W, Value_Code=3R83, ValueDisplayed=3.83
R210 R211: library part CMP-0027008-4, "RES, 0, 5%, 0.05 W, 0201", Manufacturer=Vishay-Dale, Power_W=50mW, Supplier Part Number 1=72M6743, TempCo=ppm/C, Tolerance_%=5%, Value2=0.05W, Value_Code=0000, ValueDisplayed=0
S2: library part CMP-0002163-2, "Switch, Slide, SPST, Top Slide, SMT", CurrentRating_mA=100A, Manufacturer="Copal Electronics", Supplier Part Number 1=563-1004-1-ND
SW1 SW2: library part CMP-0002325-1, "Switch, SPST-NO, Off-Mom, 0.01 A, 32 VDC, SMD", CurrentRating_mA=10A, Manufacturer="C&K Components", Supplier Part Number 1=401-1432-2-ND
U1: library part CMP-0079267-1, "2.3V-3.6V, 16M-BIT [x 1/x 2/x 4] CMOS FLASH Memory, WSON-8", Manufacturer="Macronix International Co., LTD", Supplier Part Number 1=1092-1211-ND
U2: library part CMP-0077311-2, "Single-Chip 77- and 79-GHz FMCW Radar Sensor, ABL0161B (FCBGA-161)", Alternate Manufacturer="Texas Instruments", PartNumber=AWR1642ABIGABLQ1
U3: library part CMP-0075992-1, "Automotive Fault Protected CAN Transceiver With Flexible Data-Rate, D0008A (SOIC-8)", Alternate Manufacturer="Texas Instruments", Alternate PartNumber=TCAN1042HGVDRQ1
U4: library part CMP-0073870-2, "Automotive Low-Noise, Wide-Bandwidth, High PSRR, Low-Dropout 1-A Linear Regulator, DRB0008A (VSON-8)", Alternate Manufacturer="Texas Instruments"
U5: library part CMP-0073732-2, "Dual, 1-A, Low Noise (3.8-uVRMS), LDO Voltage Regulator, RTJ0020D (WQFN-20)", Alternate Manufacturer="Texas Instruments", Alternate PartNumber=TPS7A8801RTJT
U6: library part CMP-0029856-2, "Tiva C Series Microcontroller, 1024 KB Flash, 256 KB SRAM, 12 Bit, 20 Channels, -40 to 105 degC, 128-Pin TQFP (PDT), Green (RoHS & no Sb/Br), Tray", Manufacturer="Texas Instruments", Temperature Range="-40 to 105 degC"
U7: library part CMP-0033001-1, "Precision Micropower Shunt Voltage Reference, 0.5% accuracy, 2.5 V, 15 ppm / degC, 15 mA, -40 to 125 degC, 3-pin SOT-23 (DBZ), Green (RoHS & no Sb/Br)", Manufacturer="Texas Instruments", Rating=Catalog, Temp Coeff(Max)(ppm/ degree C)=100, Temp Coeff(Typ)(ppm/ degree C)=15
U8: library part CMP-0013883-2, "Four-Phase 2.5-A-per-Phase Buck Converter With Integrated Switches, RNF0026C (VQFN-HR-26)", Alternate Manufacturer="Texas Instruments"
U9 U11: library part CMP-0036402-2, "Single Output High PSRR LDO, 1 A, Adjustable 1.2 to 5.5 V Output, 2.7 to 5.5 V Input, 8-pin SON (DRB), -40 to 125 degC, Green (RoHS & no Sb/Br)", Manufacturer="Texas Instruments"
U10: library part CMP-0043115-1, "ESD-Protection Array for High-Speed Data Interfaces, 4 Channels, -40 to +85 degC, 6-pin SON (DRY), Green (RoHS & no Sb/Br)", Breakdown Voltage(Min)(V)=6, IO Capacitance(Typ)(pF)=1.6, IO Leakage Current(nA)=1, Manufacturer="Texas Instruments"
U12 U13: library part CMP-0067397-2, "1.4V-Capable +/-0.5degC Temperature Sensor with Alert Function and I2C/SMBus interface in SOT-563, DRL0006A (SOT-OTHER-6)", Alternate Manufacturer="Texas Instruments", Alternate PartNumber=TMP112AIDRLT
U14: library part CMP-0067415-1, "10-Ohm Quad SPDT Analog Switch, RSV0016A (UQFN-16)", Alternate Manufacturer="Texas Instruments"
Y1: library part CMP-0004694-3, "Crystal, 40 MHz, 8pF, SMD", Frequency_Fixed=40MHz, Frequency Stability=+/-200ppm, Manufacturer=Kyocera, Supplier Part Number 1=581-CX3225SA40D0PTWC
Y2: library part CMP-0078214-2, "Crystal, 16 MHz, 15 ppm, 8 pF, AEC-Q200 Grade 1, SMD", Frequency_Fixed=16MHz, Frequency Stability="150 ppm", Frequency Tolerance="10 ppm", Load Capacitance="7.36 pF", Manufacturer=NDK, Supplier Part Number 1=644-1129-1-ND
ZZ1: library part AssemblyNoteLabel, Alternate Manufacturer=-
ZZ2 ZZ3 ZZ4 ZZ5: library part AssemblyNote, Alternate Manufacturer=-

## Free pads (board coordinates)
  round 275.59 / inner round 204.72 / far side round 275.59 hole 157.48: 1(2646.7,406.05) 2(2646.7,2306.05)
  round 160 hole 160 unplated mask+5: ""(102.75,162.5) ""(102.75,1570.6) ""(102.75,2402.5) ""(3136.31,162.5) ""(3136.31,2402.5)

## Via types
v1: diameter 22.4, hole 12.2, TOP to BOTTOM, tented both sides, 1046 vias
v2: diameter 13.77/15.74 (per signal layer), hole 5.9, TOP to L2-GND1, tented both sides, 699 vias
v3: diameter 19.68, hole 7.87, TOP to BOTTOM, tented both sides, 9 vias
v4: diameter 15.74, hole 5.9, TOP to L2-GND1, tented both sides, 1 vias

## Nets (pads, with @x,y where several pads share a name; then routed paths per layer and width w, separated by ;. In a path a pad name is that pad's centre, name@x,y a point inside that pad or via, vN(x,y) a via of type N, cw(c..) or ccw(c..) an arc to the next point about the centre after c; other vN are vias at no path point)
3V3_BRD: C41.2 C42.2 C43.2 C50.2 C61.2 C76.2 C77.2 C78.2 R3.2 R124.2 R127.2 R134.2 R140.2 R155.2 R156.2 R196.2 R197.2 R200.2 R201.2 U6.7 U6.8 U6.16 U6.26 U6.28 U6.39 U6.47 U6.51 U6.52 U6.69 U6.79 U6.90 U6.101 U6.113 U6.122 U9.3 U9.4 | length 6414.3
  TOP w15: v1(282.25,1045.5) 287.65,1050.9 R201.2@287.65,1073.71 301.46,1059.9 R200.2@325.45,1059.9 ; v1(1484.6,1080.35) 1484.6,1102.25 1532.35,1150 1611.55,1150 1628.76,1167.21 1629.15,1167.6 1629.15,1158.6 1712.65,1075.1 1712.65,1032.1 1755.65,989.1 1812.05,989.1 1890.65,1067.7 R196.2@1890.65,1125.31 R196.2@1890.65,1126.1
  TOP w20: R197.2@280.55,1160 R197.2@280.55,1159.21 280.55,1136.4 253.15,1109 253.15,1065.5 273.15,1045.5 v1(282.25,1045.5)
  L3-GND/SIG w15: v1(747.85,1061.4) 787.85,1101.4 866.37,1101.4 948.67,1183.7 1059.99,1183.7 1081.59,1162.1 1401.18,1162.1 1408.6,1154.68 1410.27,1154.68 v1(1484.6,1080.35)
  BOTTOM w7: 264.6,1560.15 311.39,1560.15 356.09,1560.15 ; 268.98,1402.67 U6.16@311.39,1402.67 358.32,1402.67 ; 274.11,1591.64 U6.28@311.39,1591.64 356.99,1591.64 ; U6.7@311.39,1260.93 360,1260.93 368.42,1269.35 361.09,1276.68 U6.8@311.39,1276.68 ; 464.93,1062.48 U6.122@464.93,1107.39 464.93,1153.92 ; 464.93,1674.68 U6.39@464.93,1713.69 464.93,1758.48 ; U6.47@590.92,1713.69 590.92,1745 602.43,1756.51 ; U6.113@606.67,1107.39 606.67,1137.06 623.61,1154 ; U6.51@653.91,1713.69 653.91,1767.91 660.86,1774.86 661.05,1775.05 661.24,1774.86 669.66,1766.44 U6.52@669.66,1713.69 ; 795.64,1066 U6.101@795.64,1107.39 795.64,1157.11 ; 869.75,1261 917.62,1261 U6.90@917.69,1260.93 ; 869.88,1591.64 U6.69@917.69,1591.64 953.12,1591.64 ; 873.05,1434.16 U6.79@917.69,1434.16
  BOTTOM w8: R155.2@795.64,1042.66 795.64,1043.34 795.64,1066 ; 953.12,1591.64 967.86,1576.9 995.5,1576.9
  BOTTOM w8.4: 462.75,1672.5 464.93,1674.68 ; R155.2@795.53,1042.55 R155.2@795.64,1042.66 ; 995.5,1576.9 996.09,1577.49
  BOTTOM w12: C50.2@248.96,1591.64 274.11,1591.64
  BOTTOM w15: C78.2@169.85,1002.35 170.04,1002.16 178.38,993.82 U9.3@178.38,953.94 ; U9.4@203.97,953.94 203.97,994.75 210.88,1001.66 C77.2@211.57,1002.35 ; C61.2@249.7,1402.56 249.81,1402.67 250.09,1402.67 268.98,1402.67
  BOTTOM w20: C78.2@169.85,1002.35 210.57,1002.35 211.57,1002.35 239.45,1002.35 282.25,1045.15 v1(282.25,1045.5) 322.05,1005.7 403.05,1005.7 441,1043.65 C76.2@464.67,1043.65 ; U9.4@203.97,953.94 227.43,953.94 260.39,920.98 R156.2@260.78,920.59 ; C50.2@248.96,1591.64 248.89,1591.71 248.7,1591.9 C50.2@248.7,1591.51 248.7,1576.05 264.6,1560.15 ; R140.2@249.3,1362.02 249.3,1402.16 C61.2@249.7,1402.56 ; 356.09,1560.15 386.6,1560.15 403.75,1543 ; 356.99,1591.64 396.89,1591.64 462.75,1657.5 462.75,1672.5 ; 358.32,1402.67 388.42,1402.67 403.75,1418 ; 368.42,1269.35 404.7,1269.35 461.55,1212.5 464.93,1212.5 ; 464.93,1062.48 464.67,1062.22 C76.2@464.67,1044.04 C76.2@464.67,1043.65 ; 464.93,1153.92 464.93,1212.5 ; 464.93,1758.48 C43.2@464.93,1772.66 ; C43.2@464.93,1772.71 465.08,1772.86 467.27,1775.05 583.89,1775.05 ; 623.61,1154 644.61,1175 777.75,1175 795.64,1157.11 816.75,1178.22 816.75,1237 840.75,1261 869.75,1261 ; R124.2@740.47,1775.45 700.87,1775.45 661.45,1775.45 661.05,1775.05 C42.2@620.97,1775.05 ; v1(747.85,1061.4) 751.36,1061.4 770.21,1042.55 ; 795.64,1066 795.53,1065.89 R155.2@795.53,1043.34 795.53,1042.55 770.21,1042.55 ; 869.88,1591.64 808.61,1591.64 792.75,1607.5 468.25,1607.5 403.75,1543 ; 873.05,1434.16 805.71,1434.16 743.55,1372 501.75,1372 475.75,1346 ; 996.09,1577.49 1004.74,1577.49 1016.3,1589.05 R134.2@1016.3,1603.1 ; 403.75,1418 403.75,1543 ; 403.75,1418 475.75,1346 ; C76.2@464.67,1043.65 490.1,1043.65 507.75,1026 507.75,1005.5 544.75,968.5 663.55,968.5 705.15,1010.1 737.76,1010.1 770.21,1042.55 ; 464.93,1212.5 487.75,1235.32 487.75,1334 475.75,1346 ; 583.89,1775.05 602.43,1756.51 620.78,1774.86 C42.2@620.97,1775.05 ; 583.89,1775.05 C42.2@620.97,1775.05
3V3_MON_XDS_1: R158.2 R159.2 U9.8 | length 106
  BOTTOM w15: R159.2@127.18,771.11 R159.2@127.18,771.9 U9.8@127.18,835.81
  BOTTOM w20: R159.2@127.18,771.11 168.29,771.11 R158.2@168.43,771.25
5V_IN: C86.2 FB1.2 FB2.2 P5.1 R34.2 R78.2 R100.2 R103.2 R115.2 R117.2 R118.1 R149.2 R176.2 R194.1 U11.1 U11.2 | length 1919.9
  TOP w20: R103.2@91.42,662.57 v1(91.42,694) ; v1(316.75,652) 318.75,652 318.75,652.66 R100.2@345.66,652.66 ; R117.2@411.36,573.55 411.75,573.94 419.75,581.94 v1(419.75,614) ; v1(634.6,1319.29) 647.65,1306.24 R194.1@647.65,1273.97 ; v1(942.75,1042.5) R78.2@1053.06,1042.5 R78.2@1053.85,1042.5 ; FB1.2@1588.03,646.07 1589.5,644.6 1598.05,644.6 1712.25,644.6 1819.15,751.5 1819.15,962.7 1943.45,1087 1993.75,1087 v1(2018.75,1112)
  TOP w30: v1(91.42,694) 70.75,694 46.75,718 46.75,822.5 R176.2@98.75,874.5
  BOTTOM w20: v1(91.42,694) 114.41,671.05 147.77,671.09 162.44,671.09 188.85,697.5 188.85,705.7 208.85,725.7 243.05,725.7 v1(316.75,652) ; v1(2018.75,1112) 2018.89,1112.14 R149.2@2018.89,1144.96 R149.2@2018.89,1145.75
  BOTTOM w30: v1(316.75,652) 381.75,652 v1(419.75,614) 419.75,577 v1(553.75,443)
  other v1: 664.75,382 612.75,384 576.75,404 455.65,1258 455.65,1290 1702.05,2302.5 1663.75,2304 1622.75,2319 1688.45,2341.4 1646.75,2347
5V_UNREG: C59.2 C60.2 C68.2 C72.2 C73.2 P5.2 R118.2 U8.9 U8.13 U8.18 U8.22 U8.26 | length 337.1
  TOP w25: v1(1832.75,594) 1818.75,594 1788.76,564.01 R118.2@1788.76,542.25 ; v1(1841.75,559) 1825,542.25 R118.2@1788.76,542.25 ; v1(1846.75,520) 1845.75,519 1812.01,519 R118.2@1788.76,542.25
  BOTTOM w10: U8.18@1728.55,1233.16 1770.41,1233.16 1773.95,1236.7 1807.25,1236.7 1820.45,1223.5 C68.2@1822.51,1223.5 1822.9,1223.5 1822.9,1253 v1(1822.75,1253)
  other v1: 1801.3,1020.3 1801.3,1052.3 1527.95,1076.8 1798.75,1083 1558.05,1084.6 1766.75,1091 1736.75,1101 1578.55,1107.4 1533.75,1114 1569.75,1370.5 1745.3,1370.3 1776.3,1370.3 1540.75,1373.5
+3.3VD: C5.2 C20.2 C84.2 C87.2 C97.2 P2.2 P3.2 P4.2 R14.2 R15.2 R16.2 R37.1 R38.2 R41.2 R43.2 R68.2 R74.2 R90.2 R91.2 R130.2 R133.2 R170.2 R171.2 R172.2 R173.2 R177.1 R206.2 U2.F15 U2.R10 U3.5 U14.14 | length 10789.5
  TOP w8: 1083.34,1356.75 1104.73,1356.75 1118.21,1343.27 1118.21,1338.17 1126.3,1330.08 U14.14@1139.03,1330.08
  TOP w10: v1(2096.75,1584.5) 2105.75,1584.5 2110.47,1589.22 U2.F15@2218.17,1589.22 ; v1(2343.95,1881) 2346.12,1878.83 U2.R10@2346.12,1819.53
  TOP w15: v1(1090.95,991.5) 1107.85,1008.4 1271.45,1008.4 1314.8,1051.75 R177.1@1349.25,1051.75
  TOP w20: R74.2@135.5,1383.64 v1(135.5,1422) ; R91.2@245.27,918.87 R91.2@245.27,919.66 245.27,963.02 v1(251.75,969.5) ; R90.2@303.21,919.19 332.96,919.19 v1(354.7,897.45) ; v1(318.75,1734.55) R68.2@348.79,1734.55 ; v1(777.72,1211.5) 777.72,1215.88 898.92,1337.08 R206.2@898.92,1379.34 881.01,1361.43 v1(848.67,1361.43) ; v1(995.9,1390.05) 997.29,1390.05 1009.36,1377.99 1009.36,1376.59 1021.92,1364.03 C97.2@1021.92,1361.93 1027.1,1356.75 1083.34,1356.75 ; v1(1090.95,991.5) 1089.24,989.79 1089.24,961.35 1089.44,961.15 U3.5@1144.06,961.15 ; R15.2@1216.75,2281.45 R15.2@1216.75,2280.66 1216.75,2234.3 v1(1223.15,2227.9) ; v1(1741.8,2033.85) 1762.45,2054.5 R43.2@1766.26,2054.5 R43.2@1767.05,2054.5 ; v1(1741.81,2190) 1765.99,2190 R38.2@1771.65,2184.34 ; C84.2@2037.05,1584.5 C84.2@2037.44,1584.5 v1(2096.75,1584.5) ; R41.2@2240.2,2113.48 2240.2,2109.6 2260.2,2089.6 2260.95,2089.6 v1(2260.95,2088.1) ; R37.1@2252.25,2208.8 2266.15,2208.8 2283.25,2191.7 2283.25,2147.1 v1(2268.55,2132.4) ; C5.2@2314.7,1910.8 2316.6,1908.9 2344.55,1908.9 2358.05,1922.4 C87.2@2364.55,1922.4
  L3-GND/SIG w20: v1(848.67,1361.43) 967.28,1361.43 v1(995.9,1390.05) ; v1(862.63,370.88) 863.69,369.82 v1(972.93,369.82) 980.11,377 1373.55,377 1407.75,342.8 v1@1407.75,273 ; v1(1483.75,1807) 1483.75,1828.8 1642.95,1988 1717.35,1988 1741.8,2012.45 v1(1741.8,2033.85) ; v1(1741.81,2190) 1754.21,2177.6 2068.35,2177.6 2113.55,2132.4 v1(2268.55,2132.4)
  L3-GND/SIG w30: P4.2@921.19,931.25 1030.7,931.25 1087.75,874.2 1087.75,806.4 1133.65,760.5 v1(1155.75,760.5)
  L3-GND/SIG w35: v1(135.5,1422) 176.1,1381.4 241.45,1381.4 308.15,1314.7 308.15,1193.4 344.45,1157.1 344.45,1044 269.95,969.5 v1(251.75,969.5) 251.75,932.01 286.03,897.73 354.42,897.73 v1(354.7,897.45) 389.17,931.92 411.67,931.92 ; P4.2@921.19,931.25 921.19,960.94 995.65,1035.4 1059.75,1035.4 1090.95,1004.2 v1(1090.95,991.5)
  L3-GND/SIG w40: 411.67,931.92 P3.2@511.75,931.92 512.08,932.25 P2.2@715.19,932.25 717.44,930 919.94,930 P4.2@921.19,931.25
  L4-GND/SIG w20: v1(135.5,1422) 318.75,1605.25 v1(318.75,1734.55) ; v1(702.75,2012) 656.55,1965.8 589.35,1965.8 543.25,2011.9 510.75,2011.9 482.75,2039.9 v1(482.75,2051.5) 461.75,2072.5 461.75,2341.5 613.85,2493.6 709.65,2493.6 748.35,2454.9 909.45,2454.9 961.35,2403 975.55,2403 ; v1(1223.15,2227.9) 1217.25,2233.8 1217.25,2273 1190.45,2299.8 1078.75,2299.8 1060.35,2318.2 1060.35,2318.3 1060.25,2318.3 975.55,2403 ; v1(1741.8,2033.85) 1741.8,2034.95 1751.45,2044.6 1751.45,2180.36 v1(1741.81,2190) 1753.05,2201.24 1753.05,2410.2 1694.75,2468.5 1459.25,2468.5 1426.15,2501.6 v1(1087.35,2501.6) 1087.35,2475.1 1059.95,2447.7 1018.75,2447.7 975.55,2404.5 975.55,2403 ; v1(2096.75,1584.5) 2105.75,1593.5 2189.25,1593.5 2238.15,1642.4 2238.15,1775.2 v1(2343.95,1881) 2343.95,2005.1 v1(2260.95,2088.1) 2260.95,2124.8 v1(2268.55,2132.4)
  L4-GND/SIG w40: v1(777.72,1211.5) 777.72,1174.02 905.55,1046.19 905.55,1027.09 921.19,1011.45 P4.2@921.19,931.25
  BOTTOM w20: v1(318.75,1734.55) 318.75,1832.5 388.25,1902 388.25,1957 v1(482.75,2051.5) ; v1(702.75,2012) 706.25,2008.5 R16.2@732.06,2008.5 R16.2@732.85,2008.5 ; R173.2@862.63,342.55 R173.2@862.63,343.34 v1(862.63,370.88) ; v1(972.93,369.82) R172.2@972.93,343.34 972.93,342.55 1018.11,342.55 1086.05,410.49 1086.05,732 1114.55,760.5 v1(1155.75,760.5) ; v1(1087.35,2501.6) 1090.85,2505.1 R14.2@1125.96,2505.1 R14.2@1126.75,2505.1 ; v1@1407.75,273 1428.45,273 1435.55,280.1 ; R171.2@1418.12,307.45 R171.2@1418.12,306.66 1418.12,300.63 1435.55,283.2 1435.55,280.1 ; R170.2@1530.77,307.45 1503.42,280.1 1435.55,280.1
  BOTTOM w25: R130.2@1471.56,1761.21 1471.56,1794.81 v1(1483.75,1807)
  other v1: 1410.75,269.5
AR_1P3_RF1: C36.2 C37.2 C38.2 C45.2 C46.2 C47.2 R131.2 R195.2 U2.G5 U2.H5 U2.J5 U5.14 U5.15 | length 94.3
  TOP w10: U2.G5@2474.07,1614.81 U2.H5@2474.07,1640.4 U2.J5@2474.07,1665.99
  TOP w15: U2.G5@2474.07,1614.81 2487.06,1614.81 v1(2491.75,1619.5) ; U2.J5@2474.07,1665.99 v1(2497.58,1665.99)
  other v1: 1840.75,1798.5 1865.85,1822.1
AR_1P3_RF2: C28.2 C33.2 C34.2 C35.2 C57.2 C58.2 L6.2 R122.2 R137.1 R195.1 U2.C2 U2.D2 U5.11 U5.12 | length 162.3
  TOP w20: U2.C2@2550.84,1512.45 U2.D2@2550.84,1538.04 2583.51,1538.04 2623.1,1498.45 v1(2623.1,1480.6)
  TOP w25: v1(2623.1,1480.6) 2651.85,1480.6 v1(2652.85,1479.6)
  other v1: 1835.45,1973.3 1866.25,1973.2
AR_1V4_APLL: C13.2 U2.A10 | length 86.4
  TOP w12: 2341.05,1452.5 2341.05,1456.2 U2.A10@2346.12,1461.27
  TOP w20: C13.2@2329.25,1381.9 2341.05,1393.7 2341.05,1452.5
AR_1V4_SYNTH: C14.2 U2.A13 | length 121.2
  TOP w12: 2262.85,1443.1 2269.35,1449.6 U2.A13@2269.35,1461.27
  TOP w15: C14.2@2187.2,1383.4 2197.7,1393.9 2213.65,1393.9 2262.85,1443.1
AR_1V8: C12.2 C17.2 C18.2 C19.2 C39.2 C48.2 C51.2 C52.2 C53.2 C90.2 L5.2 R82.2 U2.B11 U2.B12 U2.E15 U2.F5 U2.K5 U2.R9 U4.1 U4.2 | length 1034.9
  TOP w10: v1(2168.75,1544.5) 2187.88,1563.63 U2.E15@2218.17,1563.63 ; U2.R9@2371.71,1819.53 2371.71,1856.16 v1(2381.75,1866.2)
  TOP w12: 2294.94,1431.89 U2.B12@2294.94,1486.86
  TOP w14: C90.2@2257.75,1291.8 2257.94,1291.99 2262.17,1296.22 2273.87,1296.22 2296.75,1319.1 2296.75,1404.89 2316.55,1424.69 ; C12.2@2269.95,1391 C12.2@2269.95,1391.39 2269.95,1406.9 2294.94,1431.89 ; 2316.55,1476.6 2316.55,1482.88 U2.B11@2320.53,1486.86
  TOP w15: U2.F5@2474.07,1589.22 2478.03,1589.22 2484.75,1582.5 2486.74,1582.5 2489.21,1580.03 v1(2490.75,1580.03) ; U2.K5@2474.07,1691.58 2476.73,1691.58 v1(2494.52,1709.37)
  TOP w20: v1(2235.15,1359.9) 2236.55,1361.3 2236.55,1368.7 2258.85,1391 C12.2@2269.95,1391 ; 2316.55,1424.69 2316.55,1476.6
  L3-GND/SIG w8: 2463.35,1784.3 2463.35,1734.9 2470.75,1727.5
  L3-GND/SIG w20: v1(2381.75,1866.2) 2381.75,1865.9 2463.35,1784.3 ; 2470.75,1727.5 2488.88,1709.37 v1(2494.52,1709.37)
  BOTTOM w10: v1(2207.75,1172) 2236.58,1143.17 L5.2@2242.55,1143.17
  BOTTOM w20: v1(2168.75,1544.5) 2169.05,1544.8 2202.65,1544.8 2215.4,1557.55 C53.2@2215.4,1576.5 ; C48.2@2381.75,1830.2 C48.2@2381.75,1830.59 v1(2381.75,1866.2) ; v1(2490.75,1580.03) 2493.23,1580.03 2517.9,1604.7 C51.2@2539.9,1604.7 ; v1(2494.52,1709.37) 2494.52,1711.47 2540.85,1757.8 C39.2@2545.11,1757.8 C39.2@2545.5,1757.8
  other v1: 2190.75,1133 2197.75,1207 2194.95,1239.1
AR_ANAMUX: P1.3 U2.B13 | length 2912.2
  TOP w4: v1(2201.35,1419.4) 2219.75,1419.4 2256.35,1456 2256.35,1466.2 2269.35,1479.2 U2.B13@2269.35,1486.86
  L3-GND/SIG w5: P1.3@109.02,1808.65 167.75,1749.92 167.75,1657.7 280.15,1545.3 280.15,1518.95 387.6,1411.5 435.75,1411.5 713.95,1133.3 861.91,1133.3 937.31,1208.7 1070.55,1208.7 1088.95,1190.3 1354.35,1190.3 1369.52,1205.47 1439.67,1205.47 1497.45,1263.25 1497.45,1490.28 1544.29,1537.12 1959.13,1537.12 2076.85,1419.4 v1(2201.35,1419.4)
